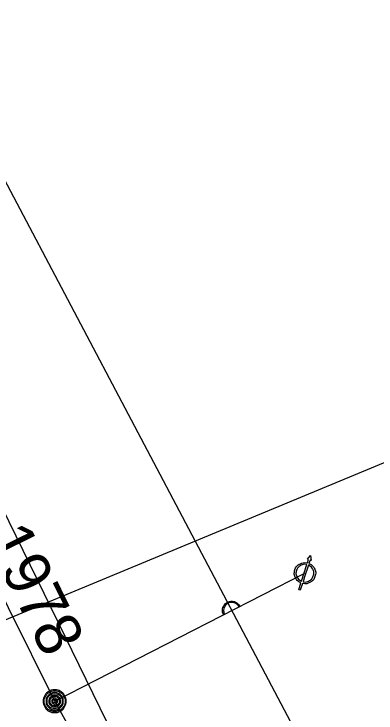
# Model space of a CAD drawing. Extents: x -595844 to -595448, y -1167192 to -1166625.
# Drawn here: x -595643.17 to -595627.33, y -1166893.94 to -1166863.38 of the extents above; entities that cross this region are included whole.
import ezdxf

# ---------------------------------------------------------------- set-up
doc = ezdxf.new("R2010")
doc.units = 0
for name, color, linetype in [('DA V Řad přejímka', 7, 'Continuous'), ('Default', 7, 'Continuous'), ('Kanalizační stoka', 7, 'Continuous'), ('V Odběrné místo', 7, 'Continuous'), ('V Přípojka', 7, 'Continuous'), ('V Řad', 7, 'Continuous'), ('VP Nepr.křížení (přípojka & řad)', 7, 'Continuous'), ('Žádost o vyjádření k existenci sítí', 7, 'Continuous')]:
    doc.layers.add(name, color=color, linetype=linetype)

msp = doc.modelspace()

# ---------------------------------------------------------------- linework, layer by layer
at = {"layer": 'Default'}
for points in [[(-595630.615, -1166888.254), (-595630.771, -1166888.191), (-595630.849, -1166888.038), (-595630.936, -1166887.868), (-595630.878, -1166887.687), (-595630.819, -1166887.506), (-595630.65, -1166887.419), (-595630.496, -1166887.341), (-595630.334, -1166887.381)], [(-595630.357, -1166887.454), (-595630.49, -1166887.423), (-595630.615, -1166887.487), (-595630.756, -1166887.56), (-595630.805, -1166887.711), (-595630.853, -1166887.862), (-595630.781, -1166888.003), (-595630.717, -1166888.128), (-595630.592, -1166888.181)], [(-595630.266, -1166887.403), (-595630.11, -1166887.465), (-595630.031, -1166887.619), (-595629.944, -1166887.789), (-595630.003, -1166887.97), (-595630.061, -1166888.151), (-595630.231, -1166888.238), (-595630.384, -1166888.316), (-595630.547, -1166888.276)], [(-595630.524, -1166888.202), (-595630.391, -1166888.233), (-595630.266, -1166888.169), (-595630.125, -1166888.097), (-595630.076, -1166887.946), (-595630.027, -1166887.795), (-595630.099, -1166887.654), (-595630.163, -1166887.528), (-595630.289, -1166887.476)], [(-595634.003, -1166889.641), (-595634.05, -1166889.548), (-595634.046, -1166889.438), (-595634.042, -1166889.328), (-595633.981, -1166889.238), (-595633.919, -1166889.149), (-595633.829, -1166889.102), (-595633.739, -1166889.056), (-595633.63, -1166889.059), (-595633.522, -1166889.061), (-595633.43, -1166889.122), (-595633.338, -1166889.183), (-595633.29, -1166889.276)], [(-595633.334, -1166889.299), (-595633.377, -1166889.217), (-595633.457, -1166889.164), (-595633.537, -1166889.111), (-595633.632, -1166889.109), (-595633.727, -1166889.107), (-595633.806, -1166889.147), (-595633.885, -1166889.187), (-595633.939, -1166889.266), (-595633.993, -1166889.344), (-595633.996, -1166889.44), (-595634, -1166889.536), (-595633.958, -1166889.618)], [(-595641.389, -1166892.925), (-595641.263, -1166892.925), (-595641.144, -1166892.99), (-595641.024, -1166893.054), (-595640.956, -1166893.175), (-595640.889, -1166893.295), (-595640.889, -1166893.426), (-595640.889, -1166893.556), (-595640.954, -1166893.675), (-595641.02, -1166893.794), (-595641.14, -1166893.86), (-595641.259, -1166893.926), (-595641.389, -1166893.926), (-595641.519, -1166893.926), (-595641.638, -1166893.86), (-595641.758, -1166893.794), (-595641.824, -1166893.675), (-595641.889, -1166893.556), (-595641.889, -1166893.426), (-595641.889, -1166893.295), (-595641.822, -1166893.175), (-595641.755, -1166893.054), (-595641.636, -1166892.99), (-595641.516, -1166892.925), (-595641.389, -1166892.925)], [(-595641.389, -1166892.972), (-595641.504, -1166892.972), (-595641.612, -1166893.03), (-595641.721, -1166893.089), (-595641.782, -1166893.198), (-595641.843, -1166893.307), (-595641.843, -1166893.426), (-595641.843, -1166893.544), (-595641.783, -1166893.652), (-595641.723, -1166893.759), (-595641.615, -1166893.819), (-595641.507, -1166893.879), (-595641.389, -1166893.879), (-595641.271, -1166893.879), (-595641.163, -1166893.819), (-595641.055, -1166893.759), (-595640.995, -1166893.652), (-595640.935, -1166893.544), (-595640.935, -1166893.426), (-595640.935, -1166893.307), (-595640.997, -1166893.198), (-595641.059, -1166893.089), (-595641.167, -1166893.03), (-595641.275, -1166892.972), (-595641.389, -1166892.972)], [(-595641.39, -1166893.05), (-595641.232, -1166893.05), (-595641.123, -1166893.16), (-595641.014, -1166893.27), (-595641.014, -1166893.426), (-595641.014, -1166893.581), (-595641.124, -1166893.691), (-595641.234, -1166893.801), (-595641.39, -1166893.801), (-595641.544, -1166893.801), (-595641.654, -1166893.691), (-595641.764, -1166893.581), (-595641.764, -1166893.426), (-595641.764, -1166893.27), (-595641.655, -1166893.16), (-595641.546, -1166893.05), (-595641.39, -1166893.05)], [(-595641.39, -1166893.096), (-595641.527, -1166893.096), (-595641.623, -1166893.192), (-595641.718, -1166893.288), (-595641.718, -1166893.425), (-595641.718, -1166893.561), (-595641.623, -1166893.657), (-595641.527, -1166893.753), (-595641.39, -1166893.753), (-595641.254, -1166893.753), (-595641.158, -1166893.657), (-595641.062, -1166893.561), (-595641.062, -1166893.425), (-595641.062, -1166893.288), (-595641.157, -1166893.192), (-595641.253, -1166893.096), (-595641.39, -1166893.096)], [(-595641.389, -1166893.175), (-595641.284, -1166893.175), (-595641.212, -1166893.249), (-595641.139, -1166893.322), (-595641.139, -1166893.426), (-595641.139, -1166893.53), (-595641.212, -1166893.603), (-595641.285, -1166893.676), (-595641.389, -1166893.676), (-595641.493, -1166893.676), (-595641.566, -1166893.603), (-595641.639, -1166893.53), (-595641.639, -1166893.426), (-595641.639, -1166893.322), (-595641.567, -1166893.249), (-595641.494, -1166893.175), (-595641.389, -1166893.175)], [(-595641.389, -1166893.222), (-595641.474, -1166893.222), (-595641.533, -1166893.281), (-595641.593, -1166893.34), (-595641.593, -1166893.425), (-595641.593, -1166893.51), (-595641.533, -1166893.569), (-595641.474, -1166893.628), (-595641.389, -1166893.628), (-595641.305, -1166893.628), (-595641.246, -1166893.569), (-595641.186, -1166893.51), (-595641.186, -1166893.425), (-595641.186, -1166893.34), (-595641.246, -1166893.281), (-595641.305, -1166893.222), (-595641.389, -1166893.222)], [(-595641.389, -1166893.3), (-595641.337, -1166893.3), (-595641.3, -1166893.337), (-595641.264, -1166893.374), (-595641.264, -1166893.426), (-595641.264, -1166893.477), (-595641.301, -1166893.514), (-595641.337, -1166893.551), (-595641.389, -1166893.551), (-595641.441, -1166893.551), (-595641.477, -1166893.514), (-595641.514, -1166893.477), (-595641.514, -1166893.426), (-595641.514, -1166893.374), (-595641.478, -1166893.337), (-595641.441, -1166893.3), (-595641.389, -1166893.3)], [(-595641.389, -1166893.347), (-595641.422, -1166893.347), (-595641.445, -1166893.37), (-595641.468, -1166893.392), (-595641.468, -1166893.426), (-595641.468, -1166893.458), (-595641.445, -1166893.481), (-595641.422, -1166893.504), (-595641.389, -1166893.504), (-595641.356, -1166893.504), (-595641.334, -1166893.481), (-595641.311, -1166893.458), (-595641.311, -1166893.426), (-595641.311, -1166893.392), (-595641.334, -1166893.37), (-595641.356, -1166893.347), (-595641.389, -1166893.347)]]:
    msp.add_open_spline(points, degree=3, dxfattribs=at)
at = {"layer": 'Kanalizační stoka'}
msp.add_lwpolyline([(-595638.8, -1166894.96), (-595639.705, -1166893.108), (-595644.306, -1166883.696), (-595652.35, -1166867.24)], dxfattribs=at)
at = {"layer": 'V Odběrné místo'}
for points in [[(-595630.334, -1166887.381), (-595630.286, -1166887.234)], [(-595630.286, -1166887.234), (-595630.331, -1166887.219), (-595630.192, -1166887.061), (-595630.172, -1166887.271), (-595630.218, -1166887.256), (-595630.266, -1166887.403)], [(-595630.592, -1166888.181), (-595630.472, -1166887.809), (-595630.357, -1166887.454)], [(-595630.289, -1166887.476), (-595630.456, -1166887.994), (-595630.524, -1166888.202)], [(-595630.547, -1166888.276), (-595630.643, -1166888.573), (-595630.711, -1166888.551), (-595630.615, -1166888.254)]]:
    msp.add_lwpolyline(points, dxfattribs=at)
at = {"layer": 'V Přípojka'}
msp.add_lwpolyline([(-595641.389, -1166893.426), (-595630.44, -1166887.829)], dxfattribs=at)
at = {"layer": 'V Řad'}
for points in [[(-595659.962, -1166819.904), (-595665.771, -1166828.627), (-595618.406, -1166918.339), (-595500.095, -1167092.442), (-595451.367, -1167161.834), (-595448.352, -1167189.877), (-595448.095, -1167192.047)], [(-595580.244, -1167001.649), (-595582.386, -1166995.003), (-595585.773, -1166985.1), (-595587.02, -1166981.54), (-595592.173, -1166969.147), (-595592.47, -1166968.66), (-595598.14, -1166960.1), (-595611.403, -1166940.363), (-595614.434, -1166935.8), (-595618.09, -1166930.49), (-595624.497, -1166921.165), (-595629.115, -1166914.569), (-595630.08, -1166913.15), (-595633.53, -1166907.61), (-595641.389, -1166893.426), (-595643.409, -1166889.34), (-595645.806, -1166884.312), (-595654.735, -1166865.632), (-595656.07, -1166862.93), (-595657.87, -1166859.03), (-595661.513, -1166851.376), (-595669.679, -1166834.367), (-595672.3, -1166829.04), (-595674.63, -1166824.09)]]:
    msp.add_lwpolyline(points, dxfattribs=at)
at = {"layer": 'VP Nepr.křížení (přípojka & řad)'}
for points in [[(-595633.29, -1166889.276), (-595633.334, -1166889.299)], [(-595633.958, -1166889.618), (-595634.003, -1166889.641)]]:
    msp.add_lwpolyline(points, dxfattribs=at)
at = {"layer": 'Žádost o vyjádření k existenci sítí'}
msp.add_lwpolyline([(-595615.986, -1166805.521), (-595674.806, -1166838.365), (-595648.233, -1166891.812), (-595604.341, -1166873.598)], close=True, dxfattribs=at)

# ---------------------------------------------------------------- texts
at = {"layer": 'DA V Řad přejímka'}
msp.add_text('1978', height=2, rotation=296.3338, dxfattribs=at).set_placement((-595644.447, -1166886.269))

doc.saveas('drawing.dxf')
